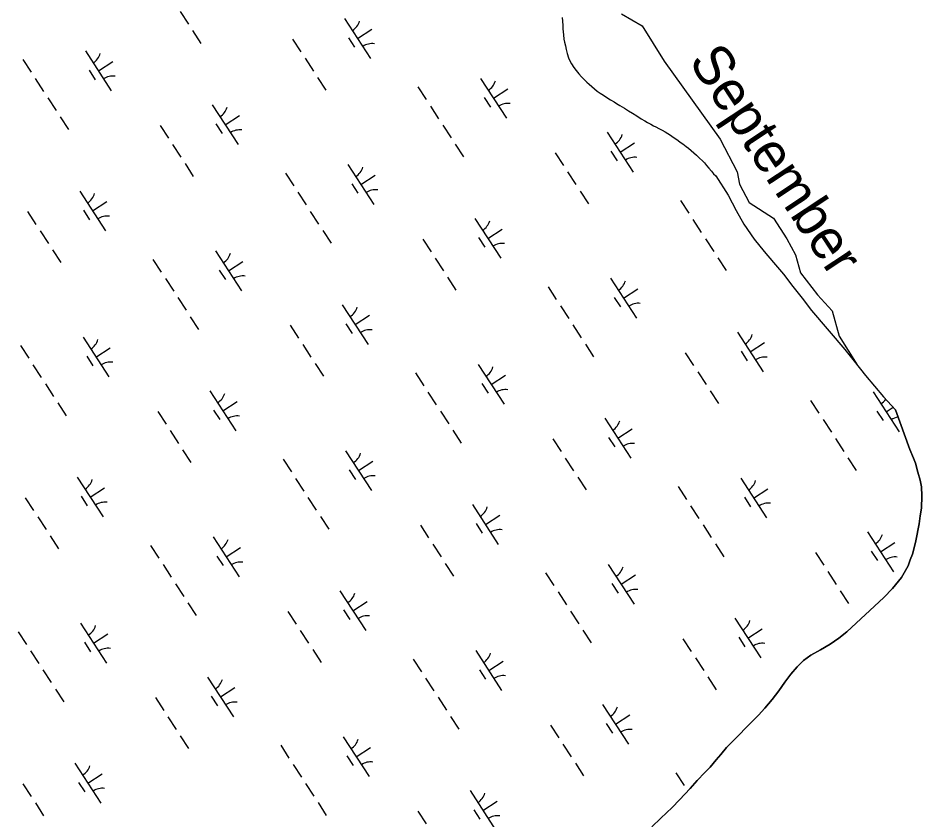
# Model space of a CAD drawing. Extents: x 3953924 to 3974542, y 193747 to 216192.
# Drawn here: x 3963049 to 3964000, y 203017 to 203861 of the extents above; entities that cross this region are included whole.
import ezdxf

# ---------------------------------------------------------------- set-up
doc = ezdxf.new("R2010")
doc.units = 0
for name, color, linetype in [('V-RIVR-EDGE', 7, 'Continuous'), ('V-RIVR-IDEN', 7, 'Continuous'), ('V-TOPO-SHOR', 7, 'Continuous'), ('V-WETL-SWMP', 7, 'Continuous')]:
    doc.layers.add(name, color=color, linetype=linetype)

msp = doc.modelspace()

# ---------------------------------------------------------------- linework, layer by layer
at = {"layer": 'V-RIVR-EDGE'}
msp.add_lwpolyline([(3963684.18, 203865.25), (3963705.95, 203852.45), (3963729, 203815.31), (3963787.91, 203733.35), (3963805.84, 203698.77), (3963808.4, 203685.96), (3963818.65, 203666.75), (3963844.26, 203650.11), (3963858.35, 203628.33), (3963867.31, 203611.69), (3963872.43, 203592.48), (3963890.36, 203569.43), (3963905.73, 203552.78), (3963913.41, 203525.88), (3963932.13, 203495.88)], dxfattribs=at)
at = {"layer": 'V-TOPO-SHOR'}
for points in [[(3963978.84, 203272.14), (3963985.81, 203284.21), (3963987.97, 203290.52), (3963990.25, 203296.71), (3963992.56, 203304.54), (3963993.83, 203310.75), (3963997.35, 203328.6), (3963998.65, 203336.97), (3963999.83, 203345.08), (3964000.33, 203357.91), (3963999.88, 203367.45), (3963998.49, 203374.47), (3963996.11, 203382.9), (3963993.5, 203392.23), (3963991.44, 203397.61), (3963987.68, 203406.71), (3963972.44, 203448.32)], [(3963716.2, 203009.78), (3963725.63, 203018.6), (3963737.52, 203030.05), (3963745.29, 203038.01), (3963756.43, 203049.85), (3963763.7, 203058.46), (3963771.73, 203066.68), (3963777.43, 203072.54), (3963783.92, 203080.15), (3963788.72, 203085.89), (3963794.57, 203093.14), (3963828.48, 203127.24), (3963835.08, 203134.35), (3963842.88, 203143.71), (3963849.65, 203152.72), (3963855.92, 203161.86), (3963862.29, 203170.11), (3963869.17, 203178.09), (3963875.64, 203184.57), (3963883.49, 203190.38), (3963893.75, 203196.02), (3963903.89, 203201.91), (3963913.02, 203208.2), (3963921.27, 203214.77), (3963960.28, 203250.8), (3963969.35, 203260.27), (3963978.84, 203272.14)]]:
    msp.add_lwpolyline(points, dxfattribs=at)
at = {"layer": 'V-WETL-SWMP'}
for p, q in [((3963219.86, 203867.63), (3963228.59, 203854.22)), ((3963392.92, 203860.18), (3963420.2, 203818.27)), ((3963621.94, 203861.21), (3963622.04, 203857.4)), ((3963406.56, 203839.22), (3963421.64, 203849.04)), ((3963622.04, 203857.4), (3963622.39, 203852.96)), ((3963622.39, 203852.96), (3963622.62, 203849.39)), ((3963622.62, 203849.39), (3963622.97, 203846.06)), ((3963232.96, 203847.52), (3963241.69, 203834.11)), ((3963396.82, 203840.04), (3963403.36, 203829.99)), ((3963622.97, 203846.06), (3963623.08, 203842.99)), ((3963623.08, 203842.99), (3963623.67, 203838.55)), ((3963338.16, 203838.5), (3963346.89, 203825.09)), ((3963623.67, 203838.55), (3963624.15, 203835.22)), ((3963624.15, 203835.22), (3963625.12, 203831.52)), ((3963625.12, 203831.52), (3963626.08, 203827.46)), ((3963120.09, 203826.05), (3963147.37, 203784.14)), ((3963626.08, 203827.46), (3963627.17, 203823.39)), ((3963627.17, 203823.39), (3963628.62, 203818.83)), ((3963054.27, 203817.12), (3963063, 203803.71)), ((3963133.73, 203805.1), (3963148.82, 203814.91)), ((3963351.26, 203818.38), (3963359.98, 203804.97)), ((3963628.62, 203818.83), (3963629.84, 203815.86)), ((3963629.84, 203815.86), (3963631.67, 203812.41)), ((3963631.67, 203812.41), (3963634.23, 203808.7)), ((3963123.99, 203805.91), (3963130.54, 203795.86)), ((3963634.23, 203808.7), (3963636.68, 203805.36)), ((3963636.68, 203805.36), (3963639.37, 203802.03)), ((3963639.37, 203802.03), (3963642.19, 203798.81)), ((3963067.37, 203797), (3963076.09, 203783.59)), ((3963364.35, 203798.27), (3963373.08, 203784.86)), ((3963535.81, 203797.22), (3963563.09, 203755.31)), ((3963642.19, 203798.81), (3963645, 203796.09)), ((3963645, 203796.09), (3963647.7, 203793.37)), ((3963647.7, 203793.37), (3963650.27, 203791.01)), ((3963469.99, 203788.28), (3963478.72, 203774.88)), ((3963549.45, 203776.26), (3963564.53, 203786.08)), ((3963650.27, 203791.01), (3963652.85, 203788.66)), ((3963652.85, 203788.66), (3963655.67, 203786.18)), ((3963655.67, 203786.18), (3963658.61, 203783.95)), ((3963658.61, 203783.95), (3963661.8, 203781.72)), ((3963080.46, 203776.89), (3963089.19, 203763.48)), ((3963539.71, 203777.08), (3963546.25, 203767.03)), ((3963661.8, 203781.72), (3963665.24, 203779.49)), ((3963665.24, 203779.49), (3963668.92, 203777.01)), ((3963668.92, 203777.01), (3963672.6, 203774.77)), ((3963672.6, 203774.77), (3963676.4, 203772.41)), ((3963253.51, 203769.43), (3963280.79, 203727.53)), ((3963483.08, 203768.17), (3963491.81, 203754.76)), ((3963676.4, 203772.41), (3963678.98, 203770.68)), ((3963678.98, 203770.68), (3963682.54, 203768.69)), ((3963682.54, 203768.69), (3963687.33, 203765.83)), ((3963687.33, 203765.83), (3963691.62, 203763.23)), ((3963093.55, 203756.77), (3963102.28, 203743.36)), ((3963267.15, 203748.48), (3963282.24, 203758.3)), ((3963691.62, 203763.23), (3963695.92, 203760.5)), ((3963695.92, 203760.5), (3963700.21, 203757.77)), ((3963700.21, 203757.77), (3963705, 203754.79)), ((3963705, 203754.79), (3963708.81, 203752.43)), ((3963198.76, 203747.75), (3963207.49, 203734.34)), ((3963257.41, 203749.3), (3963263.96, 203739.24)), ((3963496.17, 203748.06), (3963504.9, 203734.65)), ((3963708.81, 203752.43), (3963711.75, 203750.81)), ((3963711.75, 203750.81), (3963714.95, 203748.95)), ((3963714.95, 203748.95), (3963717.77, 203747.46)), ((3963717.77, 203747.46), (3963720.47, 203746.09)), ((3963720.47, 203746.09), (3963723.66, 203744.6)), ((3963723.66, 203744.6), (3963727.1, 203742.73)), ((3963669.23, 203740.6), (3963696.51, 203698.7)), ((3963727.1, 203742.73), (3963730.17, 203741.11)), ((3963730.17, 203741.11), (3963732.87, 203739.38)), ((3963732.87, 203739.38), (3963735.69, 203737.39)), ((3963735.69, 203737.39), (3963738.52, 203735.41)), ((3963738.52, 203735.41), (3963741.22, 203733.79)), ((3963211.85, 203727.64), (3963220.58, 203714.23)), ((3963509.27, 203727.94), (3963518, 203714.53)), ((3963682.87, 203719.65), (3963697.95, 203729.47)), ((3963741.22, 203733.79), (3963743.67, 203731.94)), ((3963743.67, 203731.94), (3963746.12, 203730.2)), ((3963746.12, 203730.2), (3963748.58, 203728.34)), ((3963748.58, 203728.34), (3963752.13, 203725.61)), ((3963752.13, 203725.61), (3963754.71, 203723.63)), ((3963614.47, 203718.92), (3963623.2, 203705.51)), ((3963673.13, 203720.47), (3963679.67, 203710.41)), ((3963754.71, 203723.63), (3963757.41, 203721.4)), ((3963757.41, 203721.4), (3963760.23, 203718.93)), ((3963760.23, 203718.93), (3963763.04, 203716.45)), ((3963763.04, 203716.45), (3963766.35, 203713.35)), ((3963224.94, 203707.53), (3963233.67, 203694.12)), ((3963396.4, 203706.47), (3963423.68, 203664.57)), ((3963766.35, 203713.35), (3963769.29, 203710.51)), ((3963769.29, 203710.51), (3963771.38, 203708.28)), ((3963771.38, 203708.28), (3963773.7, 203705.68)), ((3963330.58, 203697.54), (3963339.31, 203684.13)), ((3963627.57, 203698.81), (3963636.3, 203685.4)), ((3963773.7, 203705.68), (3963776.27, 203702.71)), ((3963776.27, 203702.71), (3963778.84, 203699.62)), ((3963778.84, 203699.62), (3963781.04, 203696.9)), ((3963781.04, 203696.9), (3963783.37, 203694.68)), ((3963410.04, 203685.52), (3963425.13, 203695.34)), ((3963783.37, 203694.68), (3963796.44, 203674.42)), ((3963114.11, 203678.69), (3963141.39, 203636.78)), ((3963400.3, 203686.34), (3963406.85, 203676.28)), ((3963640.66, 203678.69), (3963649.39, 203665.29)), ((3963343.68, 203677.43), (3963352.41, 203664.02)), ((3963746.3, 203668.71), (3963755.03, 203655.3)), ((3963796.44, 203674.42), (3963804.77, 203658.37)), ((3963127.75, 203657.73), (3963142.83, 203667.55)), ((3963059.35, 203657.01), (3963068.08, 203643.6)), ((3963118.01, 203658.55), (3963124.56, 203648.5)), ((3963356.77, 203657.31), (3963365.5, 203643.9)), ((3963529.82, 203649.86), (3963557.1, 203607.95)), ((3963804.77, 203658.37), (3963812.88, 203643.72)), ((3963759.39, 203648.6), (3963768.12, 203635.19)), ((3963812.88, 203643.72), (3963823.77, 203628.13)), ((3963072.45, 203636.89), (3963081.18, 203623.49)), ((3963369.86, 203637.2), (3963378.59, 203623.79)), ((3963543.46, 203628.9), (3963558.55, 203638.72)), ((3963475.07, 203628.18), (3963483.8, 203614.77)), ((3963533.72, 203629.72), (3963540.27, 203619.67)), ((3963772.49, 203628.48), (3963781.21, 203615.07)), ((3963823.77, 203628.13), (3963834.32, 203615.21)), ((3963085.54, 203616.78), (3963094.27, 203603.37)), ((3963257, 203615.73), (3963284.28, 203573.82)), ((3963834.32, 203615.21), (3963844.01, 203603.58)), ((3963191.18, 203606.8), (3963199.91, 203593.39)), ((3963270.64, 203594.78), (3963285.72, 203604.6)), ((3963488.16, 203608.06), (3963496.89, 203594.65)), ((3963785.58, 203608.37), (3963794.31, 203594.96)), ((3963844.01, 203603.58), (3963854.57, 203591.05)), ((3963260.9, 203595.59), (3963267.45, 203585.54)), ((3963204.27, 203586.68), (3963213, 203573.27)), ((3963501.26, 203587.95), (3963509.98, 203574.54)), ((3963672.72, 203586.9), (3963699.99, 203544.99)), ((3963854.57, 203591.05), (3963864.49, 203578.4)), ((3963606.89, 203577.96), (3963615.62, 203564.56)), ((3963686.35, 203565.94), (3963701.44, 203575.76)), ((3963864.49, 203578.4), (3963874.29, 203565.88)), ((3963217.37, 203566.57), (3963226.09, 203553.16)), ((3963676.61, 203566.76), (3963683.16, 203556.71)), ((3963874.29, 203565.88), (3963884.21, 203553.1)), ((3963390.42, 203559.11), (3963417.7, 203517.21)), ((3963619.99, 203557.85), (3963628.72, 203544.44)), ((3963230.46, 203546.45), (3963239.19, 203533.04)), ((3963404.06, 203538.16), (3963419.14, 203547.98)), ((3963884.21, 203553.1), (3963919.06, 203512.01)), ((3963335.66, 203537.43), (3963344.39, 203524.02)), ((3963394.32, 203538.98), (3963400.87, 203528.92)), ((3963633.08, 203537.74), (3963641.81, 203524.33)), ((3963806.14, 203530.28), (3963833.41, 203488.38)), ((3963051.78, 203516.05), (3963060.5, 203502.64)), ((3963117.6, 203524.98), (3963144.87, 203483.08)), ((3963348.76, 203517.32), (3963357.49, 203503.91)), ((3963646.17, 203517.62), (3963654.9, 203504.21)), ((3963819.77, 203509.33), (3963834.86, 203519.15)), ((3963131.23, 203504.03), (3963146.32, 203513.85)), ((3963751.38, 203508.6), (3963760.11, 203495.19)), ((3963810.04, 203510.15), (3963816.58, 203500.09)), ((3963919.06, 203512.01), (3963929.19, 203499.71)), ((3963121.49, 203504.85), (3963128.04, 203494.79)), ((3963361.85, 203497.21), (3963370.58, 203483.8)), ((3963929.19, 203499.71), (3963940.85, 203484.48)), ((3963064.87, 203495.94), (3963073.6, 203482.53)), ((3963533.31, 203496.15), (3963560.59, 203454.25)), ((3963764.47, 203488.49), (3963773.2, 203475.08)), ((3963467.49, 203487.22), (3963476.22, 203473.81)), ((3963546.95, 203475.2), (3963562.03, 203485.02)), ((3963940.85, 203484.48), (3963959.99, 203462.25)), ((3963077.96, 203475.82), (3963086.69, 203462.41)), ((3963537.21, 203476.02), (3963543.76, 203465.96)), ((3963251.02, 203468.37), (3963278.29, 203426.46)), ((3963480.58, 203467.11), (3963489.31, 203453.7)), ((3963777.57, 203468.37), (3963786.3, 203454.97)), ((3963949.03, 203467.32), (3963976.3, 203425.42)), ((3963959.99, 203462.25), (3963972.44, 203448.32)), ((3963091.05, 203455.71), (3963099.78, 203442.3)), ((3963264.65, 203447.41), (3963279.74, 203457.23)), ((3963883.21, 203458.39), (3963891.93, 203444.98)), ((3963962.66, 203446.37), (3963969.95, 203451.11)), ((3963196.26, 203446.69), (3963204.99, 203433.28)), ((3963254.92, 203448.23), (3963261.46, 203438.18)), ((3963493.68, 203446.99), (3963502.41, 203433.58)), ((3963952.93, 203447.19), (3963959.47, 203437.13)), ((3963972.44, 203448.32), (3963987.68, 203406.71)), ((3963666.73, 203439.54), (3963694.01, 203397.63)), ((3963896.3, 203438.28), (3963905.03, 203424.87)), ((3963209.35, 203426.57), (3963218.08, 203413.17)), ((3963506.77, 203426.88), (3963515.5, 203413.47)), ((3963680.37, 203418.58), (3963695.46, 203428.4)), ((3963611.98, 203417.86), (3963620.7, 203404.45)), ((3963670.63, 203419.4), (3963677.18, 203409.35)), ((3963909.39, 203418.16), (3963918.12, 203404.75)), ((3963222.45, 203406.46), (3963231.18, 203393.05)), ((3963393.91, 203405.41), (3963421.18, 203363.5)), ((3963987.68, 203406.71), (3963991.44, 203397.61)), ((3963328.09, 203396.48), (3963336.81, 203383.07)), ((3963407.54, 203384.46), (3963422.63, 203394.28)), ((3963625.07, 203397.74), (3963633.8, 203384.33)), ((3963922.49, 203398.05), (3963931.21, 203384.64)), ((3963991.44, 203397.61), (3963993.5, 203392.23)), ((3963397.81, 203385.27), (3963404.35, 203375.22)), ((3963993.5, 203392.23), (3963996.11, 203382.9)), ((3963996.11, 203382.9), (3963998.49, 203374.47)), ((3963111.61, 203377.62), (3963138.89, 203335.72)), ((3963341.18, 203376.36), (3963349.91, 203362.95)), ((3963638.16, 203377.63), (3963646.89, 203364.22)), ((3963809.62, 203376.58), (3963836.9, 203334.67)), ((3963998.49, 203374.47), (3963999.88, 203367.45)), ((3963125.25, 203356.67), (3963140.34, 203366.49)), ((3963743.8, 203367.64), (3963752.53, 203354.24)), ((3963823.26, 203355.62), (3963838.35, 203365.44)), ((3963999.88, 203367.45), (3964000.33, 203357.91)), ((3963056.86, 203355.94), (3963065.58, 203342.53)), ((3963115.51, 203357.49), (3963122.06, 203347.43)), ((3963354.27, 203356.25), (3963363, 203342.84)), ((3963813.52, 203356.44), (3963820.07, 203346.39)), ((3964000.33, 203357.91), (3963999.83, 203345.08)), ((3963527.33, 203348.79), (3963554.6, 203306.89)), ((3963756.89, 203347.53), (3963765.62, 203334.12)), ((3963999.83, 203345.08), (3963998.65, 203336.97)), ((3963069.95, 203335.83), (3963078.68, 203322.42)), ((3963367.37, 203336.13), (3963376.09, 203322.72)), ((3963540.97, 203327.84), (3963556.05, 203337.66)), ((3963998.65, 203336.97), (3963997.35, 203328.6)), ((3963472.57, 203327.11), (3963481.3, 203313.7)), ((3963531.23, 203328.66), (3963537.77, 203318.6)), ((3963769.99, 203327.42), (3963778.72, 203314.01)), ((3963997.35, 203328.6), (3963993.82, 203310.75)), ((3963943.04, 203319.96), (3963970.32, 203278.06)), ((3963083.04, 203315.72), (3963091.77, 203302.31)), ((3963254.5, 203314.66), (3963281.78, 203272.76)), ((3963485.66, 203307), (3963494.39, 203293.59)), ((3963783.08, 203307.3), (3963791.81, 203293.89)), ((3963956.68, 203299.01), (3963971.77, 203308.83)), ((3963993.82, 203310.75), (3963992.56, 203304.54)), ((3963188.68, 203305.73), (3963197.41, 203292.32)), ((3963268.14, 203293.71), (3963283.23, 203303.53)), ((3963888.29, 203298.28), (3963897.02, 203284.87)), ((3963946.94, 203299.83), (3963953.49, 203289.77)), ((3963992.56, 203304.54), (3963990.25, 203296.71)), ((3963258.4, 203294.53), (3963264.95, 203284.47)), ((3963987.97, 203290.52), (3963985.81, 203284.21)), ((3963990.25, 203296.71), (3963987.97, 203290.52)), ((3963201.77, 203285.62), (3963210.5, 203272.21)), ((3963498.76, 203286.89), (3963507.49, 203273.48)), ((3963670.22, 203285.83), (3963697.49, 203243.93)), ((3963985.81, 203284.21), (3963978.84, 203272.14)), ((3963604.4, 203276.9), (3963613.13, 203263.49)), ((3963683.86, 203264.88), (3963698.94, 203274.7)), ((3963901.38, 203278.17), (3963910.11, 203264.76)), ((3963978.84, 203272.14), (3963969.35, 203260.27)), ((3963214.87, 203265.5), (3963223.6, 203252.09)), ((3963674.12, 203265.7), (3963680.66, 203255.64)), ((3963969.35, 203260.27), (3963960.28, 203250.8)), ((3963387.92, 203258.05), (3963415.2, 203216.14)), ((3963617.49, 203256.79), (3963626.22, 203243.38)), ((3963914.47, 203258.05), (3963923.2, 203244.65)), ((3963960.28, 203250.8), (3963921.27, 203214.77)), ((3963227.96, 203245.39), (3963236.69, 203231.98)), ((3963401.56, 203237.09), (3963416.65, 203246.91)), ((3963333.17, 203236.37), (3963341.9, 203222.96)), ((3963391.82, 203237.91), (3963398.37, 203227.86)), ((3963630.58, 203236.67), (3963639.31, 203223.26)), ((3963115.1, 203223.92), (3963142.37, 203182.01)), ((3963803.64, 203229.22), (3963830.92, 203187.31)), ((3963049.28, 203214.99), (3963058.01, 203201.58)), ((3963128.74, 203202.97), (3963143.82, 203212.79)), ((3963346.26, 203216.25), (3963354.99, 203202.85)), ((3963643.68, 203216.56), (3963652.41, 203203.15)), ((3963817.28, 203208.26), (3963832.36, 203218.08)), ((3963921.27, 203214.77), (3963913.02, 203208.2)), ((3963119, 203203.79), (3963125.54, 203193.73)), ((3963748.88, 203207.54), (3963757.61, 203194.13)), ((3963807.54, 203209.08), (3963814.08, 203199.03)), ((3963913.02, 203208.2), (3963903.89, 203201.91)), ((3963062.37, 203194.87), (3963071.1, 203181.46)), ((3963359.35, 203196.14), (3963368.08, 203182.73)), ((3963530.81, 203195.09), (3963558.09, 203153.18)), ((3963893.75, 203196.02), (3963883.49, 203190.38)), ((3963903.89, 203201.91), (3963893.75, 203196.02)), ((3963464.99, 203186.16), (3963473.72, 203172.75)), ((3963544.45, 203174.14), (3963559.54, 203183.96)), ((3963761.98, 203187.42), (3963770.7, 203174.01)), ((3963875.64, 203184.57), (3963869.17, 203178.09)), ((3963883.49, 203190.38), (3963875.64, 203184.57)), ((3963075.46, 203174.76), (3963084.19, 203161.35)), ((3963534.71, 203174.95), (3963541.26, 203164.9)), ((3963869.17, 203178.09), (3963862.29, 203170.11)), ((3963248.52, 203167.3), (3963275.8, 203125.4)), ((3963478.09, 203166.04), (3963486.81, 203152.63)), ((3963775.07, 203167.31), (3963783.8, 203153.9)), ((3963862.29, 203170.11), (3963855.92, 203161.86)), ((3963088.56, 203154.64), (3963097.29, 203141.23)), ((3963262.16, 203146.35), (3963277.24, 203156.17)), ((3963855.92, 203161.86), (3963849.65, 203152.72)), ((3963193.76, 203145.62), (3963202.49, 203132.22)), ((3963252.42, 203147.17), (3963258.96, 203137.11)), ((3963491.18, 203145.93), (3963499.91, 203132.52)), ((3963849.65, 203152.72), (3963842.88, 203143.71)), ((3963664.23, 203138.47), (3963691.51, 203096.57)), ((3963842.88, 203143.71), (3963835.08, 203134.35)), ((3963677.87, 203117.52), (3963692.96, 203127.34)), ((3963828.48, 203127.24), (3963794.57, 203093.14)), ((3963835.08, 203134.35), (3963828.48, 203127.24)), ((3963206.86, 203125.51), (3963215.58, 203112.1)), ((3963504.27, 203125.81), (3963513, 203112.4)), ((3963609.48, 203116.79), (3963618.21, 203103.38)), ((3963668.13, 203118.34), (3963674.68, 203108.28)), ((3963219.95, 203105.4), (3963228.68, 203091.99)), ((3963391.41, 203104.34), (3963418.69, 203062.44)), ((3963325.59, 203095.41), (3963334.32, 203082)), ((3963405.05, 203083.39), (3963420.13, 203093.21)), ((3963622.57, 203096.68), (3963631.3, 203083.27)), ((3963794.57, 203093.14), (3963788.72, 203085.89)), ((3963395.31, 203084.21), (3963401.85, 203074.15)), ((3963783.92, 203080.15), (3963777.43, 203072.54)), ((3963788.72, 203085.89), (3963783.92, 203080.15)), ((3963109.11, 203076.56), (3963136.39, 203034.65)), ((3963338.68, 203075.3), (3963347.41, 203061.89)), ((3963635.66, 203076.57), (3963644.39, 203063.16)), ((3963777.43, 203072.54), (3963771.73, 203066.68)), ((3963122.75, 203055.61), (3963137.84, 203065.43)), ((3963741.3, 203066.58), (3963750.03, 203053.17)), ((3963771.73, 203066.68), (3963763.7, 203058.46)), ((3963054.36, 203054.88), (3963063.09, 203041.47)), ((3963113.01, 203056.42), (3963119.56, 203046.37)), ((3963351.77, 203055.18), (3963360.5, 203041.77)), ((3963763.7, 203058.46), (3963756.43, 203049.85)), ((3963524.83, 203047.73), (3963552.11, 203005.82)), ((3963756.43, 203049.85), (3963745.29, 203038.02)), ((3963067.45, 203034.77), (3963076.18, 203021.36)), ((3963364.87, 203035.07), (3963373.6, 203021.66)), ((3963538.47, 203026.77), (3963553.55, 203036.59)), ((3963745.29, 203038.02), (3963737.52, 203030.05)), ((3963470.07, 203026.05), (3963478.8, 203012.64)), ((3963528.73, 203027.59), (3963535.28, 203017.54)), ((3963737.52, 203030.05), (3963725.63, 203018.6)), ((3963725.63, 203018.6), (3963716.2, 203009.78))]:
    msp.add_line(p, q, dxfattribs=at)
for centre, start, end in [((3963391.69, 203862.5), 302.29009, 343.83375), ((3963421.82, 203816.2), 82.29009, 123.83375), ((3963118.86, 203828.37), 302.29009, 343.83375), ((3963149, 203782.08), 82.29009, 123.83375), ((3963534.58, 203799.54), 302.29009, 343.83375), ((3963252.28, 203771.76), 302.29009, 343.83375), ((3963564.71, 203753.24), 82.29009, 123.83375), ((3963282.42, 203725.46), 82.29009, 123.83375), ((3963668, 203742.93), 302.29009, 343.83375), ((3963698.14, 203696.63), 82.29009, 123.83375), ((3963395.17, 203708.8), 302.29009, 343.83375), ((3963425.31, 203662.5), 82.29009, 123.83375), ((3963112.88, 203681.01), 302.29009, 343.83375), ((3963143.02, 203634.71), 82.29009, 123.83375), ((3963528.59, 203652.18), 302.29009, 343.83375), ((3963558.73, 203605.88), 82.29009, 123.83375), ((3963255.77, 203618.05), 302.29009, 343.83375), ((3963285.91, 203571.76), 82.29009, 123.83375), ((3963671.48, 203589.22), 302.29009, 343.83375), ((3963389.19, 203561.44), 302.29009, 343.83375), ((3963701.62, 203542.92), 82.29009, 123.83375), ((3963419.33, 203515.14), 82.29009, 123.83375), ((3963804.9, 203532.61), 302.29009, 343.83375), ((3963116.36, 203527.31), 302.29009, 343.83375), ((3963146.5, 203481.01), 82.29009, 123.83375), ((3963835.04, 203486.31), 82.29009, 123.83375), ((3963532.08, 203498.48), 302.29009, 343.83375), ((3963562.22, 203452.18), 82.29009, 123.83375), ((3963249.78, 203470.69), 302.29009, 343.83375), ((3963947.79, 203469.65), 302.29009, 325.45514), ((3963279.92, 203424.4), 82.29009, 123.83375), ((3963977.93, 203423.35), 98.89377, 123.83375), ((3963665.5, 203441.86), 302.29009, 343.83375), ((3963695.64, 203395.56), 82.29009, 123.83375), ((3963392.68, 203407.73), 302.29009, 343.83375), ((3963110.38, 203379.95), 302.29009, 343.83375), ((3963422.81, 203361.44), 82.29009, 123.83375), ((3963808.39, 203378.9), 302.29009, 343.83375), ((3963140.52, 203333.65), 82.29009, 123.83375), ((3963526.1, 203351.12), 302.29009, 343.83375), ((3963838.53, 203332.61), 82.29009, 123.83375), ((3963556.23, 203304.82), 82.29009, 123.83375), ((3963941.81, 203322.29), 302.29009, 343.83375), ((3963253.27, 203316.99), 302.29009, 343.83375), ((3963283.41, 203270.69), 82.29009, 123.83375), ((3963971.95, 203275.99), 82.29009, 123.83375), ((3963668.99, 203288.16), 302.29009, 343.83375), ((3963699.12, 203241.86), 82.29009, 123.83375), ((3963386.69, 203260.37), 302.29009, 343.83375), ((3963416.83, 203214.08), 82.29009, 123.83375), ((3963113.87, 203226.24), 302.29009, 343.83375), ((3963802.41, 203231.54), 302.29009, 343.83375), ((3963832.54, 203185.24), 82.29009, 123.83375), ((3963144, 203179.95), 82.29009, 123.83375), ((3963529.58, 203197.41), 302.29009, 343.83375), ((3963247.29, 203169.63), 302.29009, 343.83375), ((3963559.72, 203151.12), 82.29009, 123.83375), ((3963277.42, 203123.33), 82.29009, 123.83375), ((3963663, 203140.8), 302.29009, 343.83375), ((3963693.14, 203094.5), 82.29009, 123.83375), ((3963390.18, 203106.67), 302.29009, 343.83375), ((3963107.88, 203078.88), 302.29009, 343.83375), ((3963420.31, 203060.37), 82.29009, 123.83375), ((3963138.02, 203032.59), 82.29009, 123.83375), ((3963523.6, 203050.05), 302.29009, 343.83375), ((3963553.74, 203003.76), 82.29009, 123.83375)]:
    msp.add_arc(centre, 17.62, start, end, dxfattribs=at)

# ---------------------------------------------------------------- texts
at = {"layer": 'V-RIVR-IDEN'}
msp.add_text('September', height=42, rotation=303.42531, dxfattribs=at).set_placement((3963754.15, 203815.36))

doc.saveas('drawing.dxf')
